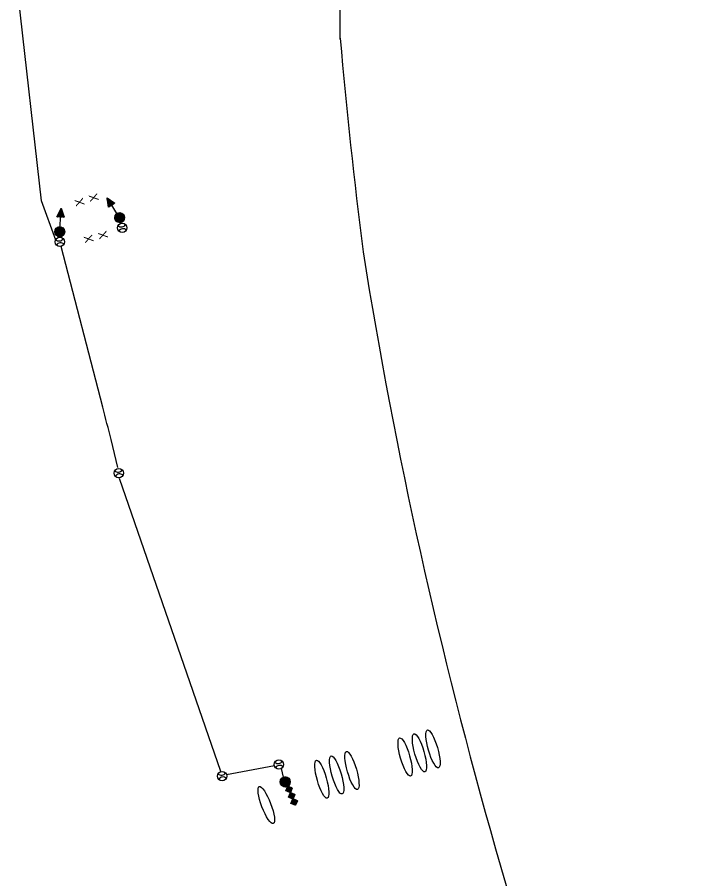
# Model space of a CAD drawing. Extents: x 601562 to 605316, y 332050 to 402250.
# Drawn here: x 601883 to 602432, y 354532 to 355227 of the extents above; entities that cross this region are included whole.
import ezdxf

# ---------------------------------------------------------------- set-up
doc = ezdxf.new("R2010")
doc.units = 0
for name, color, linetype in [('Default', 7, 'Continuous'), ('E_FTMS', 7, 'Continuous'), ('P_FTMS', 7, 'Continuous'), ('P_FTMSConduit', 7, 'Continuous')]:
    doc.layers.add(name, color=color, linetype=linetype)

# ---------------------------------------------------------------- blocks, each defined once
blk = doc.blocks.new('FMD')
at = {"layer": 'P_FTMS'}
for p, q in [((16.9, 17.6), (-16.9, 17.6)), ((-16.1, 16.1), (-16.1, 18.4)), ((16.1, 16.1), (-16.1, 16.1)), ((15.5, 19), (-15.5, 19)), ((-14.6, 14.6), (-14.6, 19.9)), ((14.6, 14.6), (-14.6, 14.6)), ((14, 20.5), (-14, 20.5)), ((-13.2, 13.2), (-13.2, 21.3)), ((13.2, 13.2), (-13.2, 13.2)), ((12.5, 21.9), (-12.5, 21.9)), ((-11.7, 11.7), (-11.7, 22.8)), ((11.7, 11.7), (-11.7, 11.7)), ((11.1, 23.4), (-11.1, 23.4)), ((-10.2, 10.2), (-10.2, 24.2)), ((10.2, 10.2), (-10.2, 10.2)), ((9.6, 24.9), (-9.6, 24.9)), ((-8.8, 8.8), (-8.8, 25.7)), ((8.8, 8.8), (-8.8, 8.8)), ((8.2, 26.3), (-8.2, 26.3)), ((-7.3, 7.3), (-7.3, 27.2)), ((7.3, 7.3), (-7.3, 7.3)), ((6.7, 27.8), (-6.7, 27.8)), ((-5.9, 5.9), (-5.9, 28.6)), ((5.9, 5.9), (-5.9, 5.9)), ((5.2, 29.3), (-5.2, 29.3)), ((-4.4, 4.4), (-4.4, 30.1)), ((4.4, 4.4), (-4.4, 4.4)), ((3.8, 30.7), (-3.8, 30.7)), ((-2.9, 2.9), (-2.9, 31.6)), ((2.9, 2.9), (-2.9, 2.9)), ((2.3, 32.2), (-2.3, 32.2)), ((-1.5, 1.5), (-1.5, 33)), ((1.5, 1.5), (-1.5, 1.5)), ((0.8, 33.6), (-0.8, 33.6)), ((0, 0), (0, 34.5)), ((1.5, 1.5), (1.5, 33)), ((2.9, 2.9), (2.9, 31.6)), ((4.4, 4.4), (4.4, 30.1)), ((5.9, 5.9), (5.9, 28.6)), ((7.3, 7.3), (7.3, 27.2)), ((8.8, 8.8), (8.8, 25.7)), ((10.2, 10.2), (10.2, 24.2)), ((11.7, 11.7), (11.7, 22.8)), ((13.2, 13.2), (13.2, 21.3)), ((14.6, 14.6), (14.6, 19.9)), ((16.1, 16.1), (16.1, 18.4))]:
    blk.add_line(p, q, dxfattribs=at)
blk.add_lwpolyline([(-17.2, 17.2), (0, 34.5), (17.2, 17.2), (0, 0)], close=True, dxfattribs=at)
blk = doc.blocks.new('_U233')
at = {"layer": 'P_FTMS'}
for p, q in [((12.1, 1.6), (-12.2, -0.1)), ((11.8, 3), (-12.1, 1.4)), ((11.9, 2.3), (-12.1, 0.6)), ((12.1, 0.8), (-12.1, -0.8)), ((12.1, 0.1), (-12.1, -1.6)), ((11.6, 3.7), (-12, 2.1)), ((-11.9, 2.5), (-11.4, -4.2)), ((11.3, 4.4), (-11.8, 2.9)), ((11, 5.2), (-11.6, 3.6)), ((10.6, 5.9), (-11.4, 4.4)), ((-11.3, 4.5), (-10.6, -6)), ((10.2, 6.6), (-11, 5.1)), ((9.8, 7.3), (-10.7, 5.9)), ((-10.7, 5.9), (-9.8, -7.2)), ((9.2, 8), (-10.2, 6.6)), ((-10, 6.9), (-9, -8.2)), ((8.6, 8.6), (-9.7, 7.4)), ((-9.3, 7.8), (-8.2, -9)), ((7.8, 9.3), (-9, 8.2)), ((-8.6, 8.5), (-7.4, -9.6)), ((6.9, 10), (-8.2, 9)), ((-8, 9.2), (-6.6, -10.2)), ((-7.3, 9.7), (-5.9, -10.6)), ((5.8, 10.7), (-7.2, 9.8)), ((-6.6, 10.3), (-5.1, -11)), ((4.5, 11.3), (-6, 10.6)), ((-5.9, 10.7), (-4.4, -11.4)), ((-5.1, 11), (-3.6, -11.6)), ((-4.4, 11.3), (-2.9, -11.8)), ((2.5, 11.9), (-4.1, 11.5)), ((-3.7, 11.6), (-2.1, -12)), ((-3, 11.8), (-1.4, -12.1)), ((-2.3, 12), (-0.6, -12.2)), ((-1.6, 12.1), (0.1, -12.2)), ((-0.8, 12.1), (0.8, -12.1)), ((-0.1, 12.2), (1.6, -12.1)), ((0.6, 12.1), (2.3, -11.9)), ((1.4, 12.1), (3, -11.8)), ((2.1, 12), (3.7, -11.6)), ((2.9, 11.8), (4.4, -11.3)), ((3.6, 11.6), (5.1, -11)), ((4.4, 11.3), (5.9, -10.7)), ((5.1, 11), (6.6, -10.2)), ((5.9, 10.6), (7.3, -9.8)), ((6.6, 10.2), (8, -9.2)), ((7.4, 9.7), (8.6, -8.6)), ((8.2, 9), (9.3, -7.8)), ((9, 8.2), (10, -6.9)), ((9.8, 7.2), (10.7, -5.8)), ((10.6, 5.9), (11.3, -4.5)), ((11.5, 4), (11.9, -2.5)), ((12.1, -0.6), (-12, -2.3)), ((12.1, -1.4), (-11.8, -3)), ((12, -2.1), (-11.6, -3.7)), ((11.8, -2.9), (-11.3, -4.4)), ((11.6, -3.6), (-11, -5.1)), ((11.3, -4.4), (-10.7, -5.9)), ((11.1, -5.1), (-10.2, -6.6)), ((10.6, -5.9), (-9.8, -7.3)), ((10.2, -6.6), (-9.2, -8)), ((9.6, -7.4), (-8.5, -8.6)), ((9, -8.2), (-7.8, -9.3)), ((8.2, -9), (-6.9, -10)), ((7.3, -9.8), (-5.8, -10.7)), ((6, -10.6), (-4.5, -11.3)), ((4.1, -11.5), (-2.6, -11.9))]:
    blk.add_line(p, q, dxfattribs=at)
blk.add_circle((0, 0), 12.2, dxfattribs=at)
blk = doc.blocks.new('POINT_DISPLAY')
at = {"layer": 'Default'}
blk.add_line((0, 0), (0, 0), dxfattribs=at)
blk = doc.blocks.new('FSGL')
at = {"layer": 'P_FTMS'}
for p, q in [((-114.3, -0.6), (-112.1, 1.6)), ((-112.1, -1.6), (-114.3, 0.6)), ((-112.8, -1.3), (-108.3, 3.2)), ((-108.3, -3.2), (-112.8, 1.3)), ((-111.3, -1.9), (-104.5, 4.8)), ((-104.5, -4.8), (-111.3, 1.9)), ((-109.8, -2.6), (-100.7, 6.5)), ((-100.7, -6.5), (-109.8, 2.6)), ((-108.3, -3.2), (-97, 8.1)), ((-97, -8.1), (-108.3, 3.2)), ((-106.8, -3.9), (-93.2, 9.7)), ((-93.2, -9.7), (-106.8, 3.9)), ((-105.3, -4.5), (-89.4, 11.3)), ((-89.4, -11.3), (-105.3, 4.5)), ((-103.8, -5.2), (-85.7, 12.9)), ((-85.7, -12.9), (-103.8, 5.2)), ((-102.2, -5.8), (-81.9, 14.5)), ((-81.9, -14.5), (-102.2, 5.8)), ((-100.7, -6.5), (-78.1, 16.2)), ((-78.1, -16.2), (-100.7, 6.5)), ((-99.2, -7.1), (-74.3, 17.8)), ((-74.3, -17.8), (-99.2, 7.1)), ((-97.7, -7.8), (-73.2, 16.8)), ((-73.2, -16.8), (-97.7, 7.8)), ((-96.2, -8.4), (-73.2, 14.7)), ((-73.2, -14.7), (-96.2, 8.4)), ((-94.7, -9.1), (-73.2, 12.5)), ((-73.2, -12.5), (-94.7, 9.1)), ((-93.2, -9.7), (-73.2, 10.3)), ((-73.2, -10.3), (-93.2, 9.7)), ((-73.2, -8.2), (-91.7, 10.3)), ((-91.7, -10.3), (-73.2, 8.2)), ((-73.2, -6), (-90.2, 11)), ((-90.2, -11), (-73.2, 6)), ((-73.2, -3.9), (-88.7, 11.6)), ((-88.7, -11.6), (-73.2, 3.9)), ((-73.2, -1.7), (-87.2, 12.3)), ((-87.2, -12.3), (-73.2, 1.7)), ((-73.2, 0.4), (-85.7, 12.9)), ((-73.2, 2.6), (-84.1, 13.6)), ((-73.2, 4.7), (-82.6, 14.2)), ((-73.2, 6.9), (-81.1, 14.9)), ((-73.2, 9.1), (-79.6, 15.5)), ((-73.2, 11.2), (-78.1, 16.2)), ((-73.2, 13.4), (-76.6, 16.8)), ((-73.2, 15.5), (-75.1, 17.5)), ((-73.2, 17.7), (-73.6, 18.1)), ((-24.6, 0), (-73.2, 0)), ((-24.3, -1.5), (1.5, 24.3)), ((-24.3, 0.5), (-0.5, 24.3)), ((1.5, -24.3), (-24.3, 1.5)), ((-24.1, -3.4), (3.4, 24.1)), ((-24.1, 2.8), (-2.7, 24.1)), ((3.4, -24.1), (-24.1, 3.4)), ((-23.8, -5.1), (5.1, 23.8)), ((-23.8, 5.1), (-5.2, 23.7)), ((5.1, -23.8), (-23.8, 5.2)), ((-23.4, -6.8), (6.8, 23.3)), ((6.8, -23.4), (-23.3, 6.8)), ((-22.9, 8.1), (-8, 23)), ((-22.8, -8.3), (8.4, 22.9)), ((8.3, -22.8), (-22.8, 8.4)), ((9.9, -22.3), (-22.3, 9.8)), ((-22.2, -9.8), (9.8, 22.2)), ((-21.6, -11.3), (11.2, 21.6)), ((11.2, -21.6), (-21.6, 11.2)), ((-21.2, 11.9), (-11.8, 21.4)), ((12.5, -20.8), (-20.9, 12.6)), ((-20.8, -12.5), (12.6, 20.8)), ((-20, -13.8), (13.8, 20)), ((13.8, -20), (-20, 13.8)), ((-19.2, -15), (15, 19.2)), ((15, -19.1), (-19.1, 15)), ((-18.2, -16.1), (16.1, 18.2)), ((16.1, -18.2), (-18.2, 16.2)), ((-17.2, -17.2), (17.2, 17.2)), ((17.2, -17.2), (-17.2, 17.2)), ((18.2, -16.1), (-16.1, 18.2)), ((-16.1, -18.2), (18.2, 16.2)), ((19.2, -15), (-15, 19.2)), ((-15, -19.1), (19.1, 15)), ((20, -13.8), (-13.8, 20)), ((-13.8, -20.1), (20, 13.8)), ((20.8, -12.5), (-12.6, 20.8)), ((-12.5, -20.8), (20.9, 12.6)), ((21.6, -11.3), (-11.2, 21.6)), ((-11.2, -21.6), (21.6, 11.2)), ((-9.9, -22.3), (22.2, 9.8)), ((22.2, -9.8), (-9.8, 22.2)), ((22.8, -8.3), (-8.4, 22.9)), ((-8.3, -22.8), (22.9, 8.4)), ((23.4, -6.8), (-6.8, 23.3)), ((-6.8, -23.4), (23.3, 6.8)), ((23.8, -5.1), (-5.1, 23.8)), ((-5.1, -23.8), (23.8, 5.2)), ((24.1, -3.4), (-3.4, 24.1)), ((-3.4, -24.1), (24.1, 3.4)), ((24.3, -1.5), (-1.5, 24.3)), ((-1.5, -24.3), (24.3, 1.5)), ((24.3, 0.5), (0.5, 24.3)), ((24.1, 2.8), (2.7, 24.1)), ((23.8, 5.1), (5.2, 23.8)), ((22.9, 8.1), (8, 23)), ((21.2, 11.9), (11.8, 21.3)), ((-85.7, -12.9), (-73.2, -0.4)), ((-84.1, -13.6), (-73.2, -2.6)), ((-82.6, -14.2), (-73.2, -4.7)), ((-81.1, -14.9), (-73.2, -6.9)), ((-79.6, -15.5), (-73.2, -9.1)), ((-78.1, -16.2), (-73.2, -11.2)), ((-76.6, -16.8), (-73.2, -13.4)), ((-75.1, -17.5), (-73.2, -15.5)), ((-73.6, -18.1), (-73.2, -17.7)), ((-0.5, -24.3), (-24.3, -0.5)), ((-2.7, -24.2), (-24.2, -2.7)), ((-5.2, -23.8), (-23.7, -5.2)), ((-8.1, -22.9), (-22.9, -8.1)), ((-12, -21.2), (-21.2, -11.9)), ((0.5, -24.3), (24.3, -0.5)), ((2.7, -24.2), (24.2, -2.7)), ((5.2, -23.8), (23.7, -5.2)), ((8.1, -22.9), (22.9, -8.1)), ((12, -21.2), (21.2, -11.9))]:
    blk.add_line(p, q, dxfattribs=at)
blk.add_lwpolyline([(-73.2, -18.3), (-115.8, 0), (-73.2, 18.3)], close=True, dxfattribs=at)
blk.add_circle((0, 0), 24.4, dxfattribs=at)
blk.add_blockref('POINT_DISPLAY', (-115.8, 0), dxfattribs=at)

msp = doc.modelspace()

# ---------------------------------------------------------------- linework, layer by layer
at = {"layer": 'P_FTMS'}
for centre in [(601967.2, 355057.43), (601916.91, 355046.11), (601964.4, 354859.66), (602093.48, 354624.6), (602047.73, 354615.23)]:
    msp.add_circle(centre, 3.75, dxfattribs=at)
for centre, start, end in [((601966.6, 355061.89), 224.54439, 330.80004), ((601967.8, 355052.97), 44.54439, 150.80004), ((601916.3, 355050.57), 224.54439, 330.80004), ((601917.51, 355041.65), 44.54439, 150.80004), ((601963.8, 354864.12), 224.54439, 330.80004), ((601965, 354855.2), 44.54439, 150.80004), ((602092.88, 354629.06), 224.54439, 330.80004), ((602094.08, 354620.14), 44.54439, 150.80004), ((602047.13, 354619.69), 224.54439, 330.80004), ((602048.33, 354610.77), 44.54439, 150.80004)]:
    msp.add_arc(centre, 3.75, start, end, dxfattribs=at)
for centre, major_axis in [((602206.74, 354633.99), (-4.43, 15.35)), ((602217.64, 354637.13), (-4.43, 15.35)), ((602195.17, 354630.65), (-4.43, 15.35)), ((602152.35, 354619.7), (-4.43, 15.35)), ((602128.08, 354612.69), (-4.43, 15.35)), ((602140.02, 354616.14), (-4.43, 15.35)), ((602083.33, 354591.83), (-5.66, 14.94))]:
    msp.add_ellipse(centre, major_axis=major_axis, ratio=0.23471, dxfattribs=at)
at = {"layer": 'P_FTMSConduit'}
for p, q in [((602142.95, 355209.66), (602142.34, 355329.01)), ((601902.2, 355079.35), (601882.6, 355252.12)), ((601913.72, 355047.54), (601902.2, 355079.35)), ((602046.61, 354618.81), (601965, 354855.2)), ((602051.29, 354616.42), (602089.8, 354623.89)), ((602097.22, 354614.36), (602095.47, 354621.41))]:
    msp.add_line(p, q, dxfattribs=at)
for points in [[(601951.45, 354912.77), (601918.13, 355042.42)], [(601963.8, 354864.12), (601958.22, 354886.62)]]:
    msp.add_lwpolyline(points, dxfattribs=at)
for centre, radius, start, end in [((606343.83, 355570.74), 4216.31, 184.90359, 187.25923), ((606226.24, 355687.63), 4116.52, 189.08016, 202.81702), ((600711.62, 354577.97), 1284.25, 13.9064, 15.11153)]:
    msp.add_arc(centre, radius, start, end, dxfattribs=at)

# ---------------------------------------------------------------- block references
at = {"layer": 'E_FTMS'}
for p, xscale, yscale, rotation in [((601965.15, 355065.68), 0.16404165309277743, 0.16404165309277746, -57.59906443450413), ((601916.84, 355054.27), 0.16404164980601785, 0.16404164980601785, -93.35166671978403)]:
    msp.add_blockref('FSGL', p, dxfattribs=dict(at, xscale=xscale, yscale=yscale, rotation=rotation))
at = {"layer": 'P_FTMS'}
for name, p, xscale, yscale, rotation in [('_U233', (602098.56, 354610.6), 0.3280833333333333, 0.3280833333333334, -153.80622439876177), ('FMD', (602104.25, 354605.59), 0.16404166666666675, 0.16404166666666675, 112.08663983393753), ('FMD', (602106.38, 354600.38), 0.16404166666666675, 0.16404166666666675, 112.08663983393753), ('FMD', (602108.37, 354595.34), 0.16404166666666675, 0.16404166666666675, 112.08663983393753)]:
    msp.add_blockref(name, p, dxfattribs=dict(at, xscale=xscale, yscale=yscale, rotation=rotation))

# ---------------------------------------------------------------- texts
at = {"layer": 'P_FTMSConduit'}
for p in [(601937, 355075.96), (601948.42, 355079.63), (601944.36, 355046.35), (601955.89, 355049.4)]:
    msp.add_text('X', height=7, rotation=104.38506, dxfattribs=at).set_placement(p)

doc.saveas('drawing.dxf')
